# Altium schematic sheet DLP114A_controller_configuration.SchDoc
size A2; DocumentNumber: 4; SheetNumber: 4; SheetTotal: 7
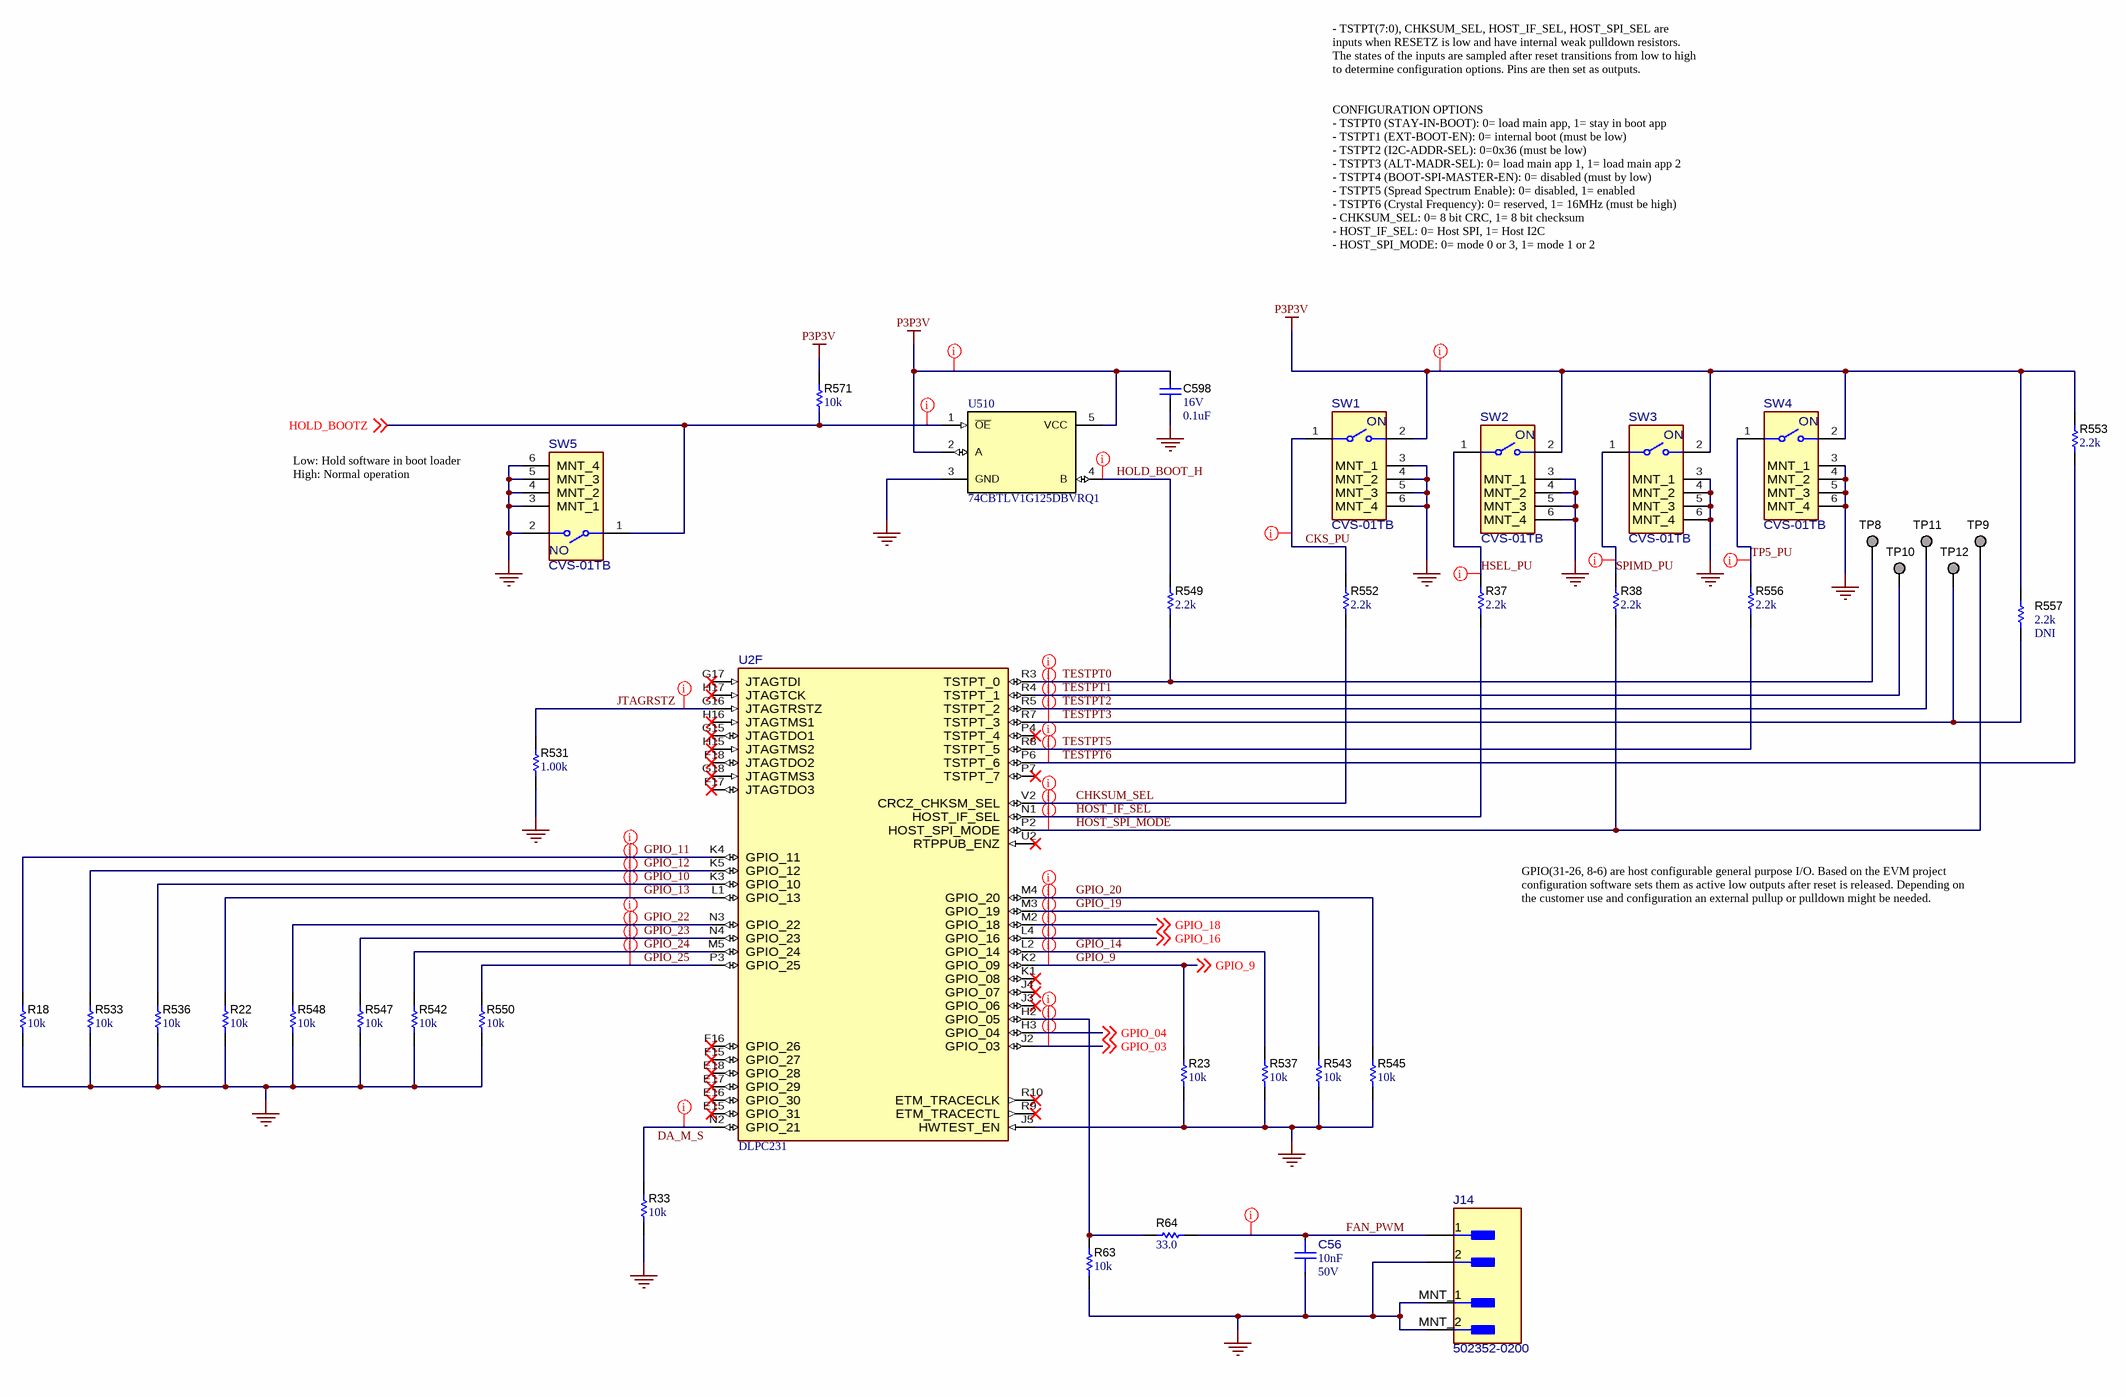
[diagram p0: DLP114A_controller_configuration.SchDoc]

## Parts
C56  ValueDisplayed: 10nF  VDC_V: 50V  [FP-GCM155R71H103KA55D_0402-MFG]  (hidden comment: GCM155R71H103KA55D)
C598  VDC_V: 16V  ValueDisplayed: 0.1uF  [0402]  (hidden comment: GCM155R71C104KA55D)
J14  502352-0200  [FP-502352-0200_HDR2-MFG]
R18  ValueDisplayed: 10k  [0402]  (hidden comment: ERJ-2GEJ103X)
R22  ValueDisplayed: 10k  [0402]  (hidden comment: ERJ-2GEJ103X)
R23  ValueDisplayed: 10k  [0402]  (hidden comment: ERJ-2GEJ103X)
R33  ValueDisplayed: 10k  [0402]  (hidden comment: ERJ-2GEJ103X)
R37  ValueDisplayed: 2.2k  [0402]  (hidden comment: CRCW04022K20JNED)
R38  ValueDisplayed: 2.2k  [0402]  (hidden comment: CRCW04022K20JNED)
R63  ValueDisplayed: 10k  [0402]  (hidden comment: ERJ-2GEJ103X)
R64  ValueDisplayed: 33.0  [0402]  (hidden comment: ERJ-2RKF33R0X)
R531  ValueDisplayed: 1.00k  [0402]  (hidden comment: CRCW04021K00FKED)
R533  ValueDisplayed: 10k  [0402]  (hidden comment: ERJ-2GEJ103X)
R536  ValueDisplayed: 10k  [0402]  (hidden comment: ERJ-2GEJ103X)
R537  ValueDisplayed: 10k  [0402]  (hidden comment: ERJ-2GEJ103X)
R542  ValueDisplayed: 10k  [0402]  (hidden comment: ERJ-2GEJ103X)
R543  ValueDisplayed: 10k  [0402]  (hidden comment: ERJ-2GEJ103X)
R545  ValueDisplayed: 10k  [0402]  (hidden comment: ERJ-2GEJ103X)
R547  ValueDisplayed: 10k  [0402]  (hidden comment: ERJ-2GEJ103X)
R548  ValueDisplayed: 10k  [0402]  (hidden comment: ERJ-2GEJ103X)
R549  ValueDisplayed: 2.2k  [0402]  (hidden comment: CRCW04022K20JNED)
R550  ValueDisplayed: 10k  [0402]  (hidden comment: ERJ-2GEJ103X)
R552  ValueDisplayed: 2.2k  [0402]  (hidden comment: CRCW04022K20JNED)
R553  ValueDisplayed: 2.2k  [0402]  (hidden comment: CRCW04022K20JNED)
R556  ValueDisplayed: 2.2k  [0402]  (hidden comment: CRCW04022K20JNED)
R557  ValueDisplayed: 2.2k  Parameter 1: DNI  [0402]  (hidden comment: CRCW04022K20JNED)
R571  ValueDisplayed: 10k  [0402]  (hidden comment: ERJ-2GEJ103X)
SW1  CVS-01TB  [FP-CVS-01TB_SMT_SW_4MM7_2MM0-MFG]
SW2  CVS-01TB  [FP-CVS-01TB_SMT_SW_4MM7_2MM0-MFG]
SW3  CVS-01TB  [FP-CVS-01TB_SMT_SW_4MM7_2MM0-MFG]
SW4  CVS-01TB  [FP-CVS-01TB_SMT_SW_4MM7_2MM0-MFG]
SW5  CVS-01TB  [FP-CVS-01TB_SMT_SW_4MM7_2MM0-MFG]
TP8  TESTPOINT  [TESTPOINT]  (value not drawn)  (no BOM)
TP9  TESTPOINT  [TESTPOINT]  (value not drawn)  (no BOM)
TP10  TESTPOINT  [TESTPOINT]  (value not drawn)  (no BOM)
TP11  TESTPOINT  [TESTPOINT]  (value not drawn)  (no BOM)
TP12  TESTPOINT  [TESTPOINT]  (value not drawn)  (no BOM)
U2  DLPC231  [ZEK0324A-MFG]  (part F of 9)
U510  74CBTLV1G125DBVRQ1  [DBV0005A_N]

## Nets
GND: C56.1 C598.2 J14.2 J14.3(MNT_1) J14.4(MNT_2) R18.1 R22.1 R23.1 R33.1 R63.1 R531.1 R533.1 R536.1 R537.1 R542.1 R543.1 R545.1 R547.1 R548.1 R550.1 SW1.3(MNT_1) SW1.4(MNT_2) SW1.5(MNT_3) SW1.6(MNT_4) SW2.3(MNT_1) SW2.4(MNT_2) SW2.5(MNT_3) SW2.6(MNT_4) SW3.3(MNT_1) SW3.4(MNT_2) SW3.5(MNT_3) SW3.6(MNT_4) SW4.3(MNT_1) SW4.4(MNT_2) SW4.5(MNT_3) SW4.6(MNT_4) SW5.2 SW5.3(MNT_1) SW5.4(MNT_2) SW5.5(MNT_3) SW5.6(MNT_4) U2.J5(HWTEST_EN) U510.3(GND)
P3P3V: C598.1 R553.2 R557.2 R571.2 SW1.2 SW2.2 SW3.2 SW4.2 U510.2(A) U510.5(VCC)
CHKSUM_SEL: R552.1 U2.V2(CRCZ_CHKSM_SEL)
CKS_PU: R552.2 SW1.1
DA_M_S: R33.2 U2.N2(GPIO_21)
FAN_PWM: C56.2 J14.1 R64.2
GPIO_03: U2.J2(GPIO_03) ; off-sheet GPIO_03
GPIO_04: U2.H3(GPIO_04) ; off-sheet GPIO_04
GPIO_9: R23.2 U2.K2(GPIO_09) ; off-sheet GPIO_9
GPIO_10: R536.2 U2.K3(GPIO_10)
GPIO_11: R18.2 U2.K4(GPIO_11)
GPIO_12: R533.2 U2.K5(GPIO_12)
GPIO_13: R22.2 U2.L1(GPIO_13)
GPIO_14: R537.2 U2.L2(GPIO_14)
GPIO_16: U2.L4(GPIO_16) ; off-sheet GPIO_16
GPIO_18: U2.M2(GPIO_18) ; off-sheet GPIO_18
GPIO_19: R543.2 U2.M3(GPIO_19)
GPIO_20: R545.2 U2.M4(GPIO_20)
GPIO_22: R548.2 U2.N3(GPIO_22)
GPIO_23: R547.2 U2.N4(GPIO_23)
GPIO_24: R542.2 U2.M5(GPIO_24)
GPIO_25: R550.2 U2.P3(GPIO_25)
HOLD_BOOT_H: R549.2 U510.4(B)
HOLD_BOOTZ: R571.1 SW5.1 U510.1(~{OE}) ; off-sheet HOLD_BOOTZ
HOST_IF_SEL: R37.1 U2.N1(HOST_IF_SEL)
HOST_SPI_MODE: R38.1 TP9.1 U2.P2(HOST_SPI_MODE)
HSEL_PU: R37.2 SW2.1
JTAGRSTZ: R531.2 U2.G16(JTAGTRSTZ)
SPIMD_PU: R38.2 SW3.1
TESTPT0: R549.1 TP8.1 U2.R3(TSTPT_0)
TESTPT1: TP10.1 U2.R4(TSTPT_1)
TESTPT2: TP11.1 U2.R5(TSTPT_2)
TESTPT3: R557.1 TP12.1 U2.R7(TSTPT_3)
TESTPT5: R556.1 U2.R8(TSTPT_5)
TESTPT6: R553.1 U2.P6(TSTPT_6)
TP5_PU: R556.2 SW4.1
NetR63_2: R63.2 R64.1 U2.H2(GPIO_05)

Not connected (* = marked no-connect by the designer): U2 E15(GPIO_31)* E16(GPIO_30)* E17(GPIO_29)* E18(GPIO_28)* F15(GPIO_27)* F16(GPIO_26)* F17(JTAGTDO3)* F18(JTAGTDO2)* G15(JTAGTDO1)* G17(JTAGTDI)* G18(JTAGTMS3)* H15(JTAGTMS2)* H16(JTAGTMS1)* H17(JTAGTCK)* J3(GPIO_06)* J4(GPIO_07)* K1(GPIO_08)* P4(TSTPT_4)* P7(TSTPT_7)* R9(ETM_TRACECTL)* R10(ETM_TRACECLK)* U2(RTPPUB_ENZ)*

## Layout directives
net class 50OHM: CHKSUM_SEL, CKS_PU, DA_M_S, FAN_PWM, GPIO_03, GPIO_04, GPIO_9, GPIO_10, GPIO_11, GPIO_12, GPIO_13, GPIO_14, GPIO_16, GPIO_18, GPIO_19, GPIO_20, GPIO_22, GPIO_23, GPIO_24, GPIO_25, HOLD_BOOT_H, HOLD_BOOTZ, HOST_IF_SEL, HOST_SPI_MODE, HSEL_PU, JTAGRSTZ, NetR63_2, SPIMD_PU, TESTPT0, TESTPT1, TESTPT2, TESTPT3, TESTPT5, TESTPT6, TP5_PU
net class POWER: P3P3V

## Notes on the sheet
- - TSTPT(7:0), CHKSUM_SEL, HOST_IF_SEL, HOST_SPI_SEL are inputs when RESETZ is low and have internal weak pulldown resistors. The states of the inputs are sampled after reset transitions from low to high to determine configuration options. Pins are then set as outputs.
- CONFIGURATION OPTIONS
  - TSTPT0 (STAY-IN-BOOT): 0= load main app, 1= stay in boot app
  - TSTPT1 (EXT-BOOT-EN): 0= internal boot (must be low)
  - TSTPT2 (I2C-ADDR-SEL): 0=0x36 (must be low)
  - TSTPT3 (ALT-MADR-SEL): 0= load main app 1, 1= load main app 2
  - TSTPT4 (BOOT-SPI-MASTER-EN): 0= disabled (must by low)
  - TSTPT5 (Spread Spectrum Enable): 0= disabled, 1= enabled
  - TSTPT6 (Crystal Frequency): 0= reserved, 1= 16MHz (must be high)
  - CHKSUM_SEL: 0= 8 bit CRC, 1= 8 bit checksum
  - HOST_IF_SEL: 0= Host SPI, 1= Host I2C
  - HOST_SPI_MODE: 0= mode 0 or 3, 1= mode 1 or 2
- Low: Hold software in boot loader
  High: Normal operation
- GPIO(31-26, 8-6) are host configurable general purpose I/O. Based on the EVM project
  configuration software sets them as active low outputs after reset is released. Depending on
  the customer use and configuration an external pullup or pulldown might be needed.

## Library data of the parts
C56 = CMP-0093287-1: Ceramic Capacitor for Automotive 10nF ±10% 50VDC X7R 0402 Paper T/R; Manufacturer: Murata; AEC Qualified: Yes; Tolerance_%: 0.1%; SizeZ_mm: 0.55mm; TempCo: 15%; AEC Grade: Grade 1
C598 = CMP-0006351-2: CAP, CERM, 0.1 uF, 16 V, +/- 10%, X7R, 0402; Manufacturer: MuRata; TaMin_C: -55°C; Polarized: N; SizeAreaWB_mm2: 3; Value1: Unknown; U/M: EA; Value: 0.1uF; TaMax_C: 125°C; SizeZ_mm: 0.6; SizeX_mm: 1; SizeY_mm: 0.5; Cap_F: 100nF; AEC Category: Q200
J14 = CMP-0087312-1: CONN HEADER SMD R/A 2POS 2MM; Manufacturer: Molex; ContactFinish: Tin,Nickel; Current_A: 3A; Voltage_V: 125V; Row_Count: 1
R18 R22 R23 R33 R63 R533 R536 R537 R542 R543 R545 R547 R548 R550 R571 = CMP-0026994-4: RES, 10 k, 5%, 0.1 W, AEC-Q200 Grade 0, 0402; Manufacturer: Panasonic; Power_W: 100mW; TempCo: 200 ppm/C; Value_Code: 10k0; U/M: EA; Value: 10k; EIA_Code: E24; SizeX_mm: 1; SizeY_mm: 0.5; SizeZ_mm: 0.6; Value2: 0.1W; AEC Qualified: Y; VDC_V: 50V; AEC Grade: 0; AEC Category: Q200
R37 R38 R549 R552 R553 R556 R557 = CMP-0026890-5: RES, 2.2 k, 5%, 0.063 W, AEC-Q200 Grade 0, 0402; Manufacturer: Vishay-Dale; Power_W: 63mW; TempCo: 200 ppm/C; Value_Code: 2k20; Value: 2.2k; EIA_Code: E24; SizeX_mm: 1; SizeY_mm: 0.5; SizeZ_mm: 0.6; Value2: 0.063W; AEC Qualified: Y; VDC_V: 50V; AEC Category: Q200; AEC Grade: 0
R64 = CMP-0026696-1: RES, 33.0, 1%, 0.1 W, 0402; Manufacturer: Panasonic; Power_W: 100mW; TempCo: 100 ppm/C; Value_Code: 33R0; U/M: EA; Value: 33.0; Res_ohm: 33; SizeX_mm: 1; SizeY_mm: 0.5; SizeZ_mm: 0.6; Value2: 0.1W; VDC_V: 50V; AEC Category: Q200
R531 = CMP-0026071-3: RES, 1.00 k, 1%, 0.063 W, AEC-Q200 Grade 0, 0402; Manufacturer: Vishay-Dale; Power_W: 63mW; TempCo: 100 ppm/C; Value_Code: 1k00; Value: 1.00k; EIA_Code: E96; Res_ohm: 1k; SizeX_mm: 1; SizeY_mm: 0.5; SizeZ_mm: 0.6; Value2: 0.063W; AEC Qualified: Y; VDC_V: 50V; AEC Category: Q200; AEC Grade: 0
SW1-SW5 = CMP-0095685-1: Switch Slide OFF ON SPST Recessed Slide 0.1A 24VDC Gull Wing SMD Embossed T/R; Manufacturer: Nidec Copal; PositionCount: 1; SizeZ_mm: 1.75mm; Standoff Height: 0mm; Contact Current Rating: 100mA; VDC_V: 24V; Coil Resistance_ohm: 200mΩ; AEC Qualified: No
TP8-TP12 = CMP-0078143-2: TEST POINT.  No entry in BOM.
U2 = CMP-0096130-1: Manufacturer: Texas Instruments; Standoff Height: 0.35mm; SizeZ_mm: 1.5mm
U510 = CMP-0050954-2: Automotive Catalog Low-Voltage Single FET Bus Switch, DBV0005A (SOT-23-5); Generic Part Number: SN74CBTLV1G125-Q1; Manufacturer: Texas Instruments; Bits(#): 1; Schmitt Trigger: No; VCC(Min)(V): 2.3; Input Type: LV-CMOS; Switch Configuration: SPST; Output Type: CMOS; F @ Nom Voltage(Max)(Mhz): 200; VCC(Max)(V): 3.6; tpd @ Nom Voltage(Max)(ns): 0.25; Logic: True; ICC @ Nom Voltage(Max)(mA): 0.01; Voltage(Nom)(V): 3.3; AEC Category: Q200; AEC Qualified: Y; CompType: IC; SizeAreaWB_mm2: 14.82; SizeArea_mm2: 8.12; SizeX_mm: 2.8; SizeY_mm: 2.9; SizeZ_mm: 1.45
